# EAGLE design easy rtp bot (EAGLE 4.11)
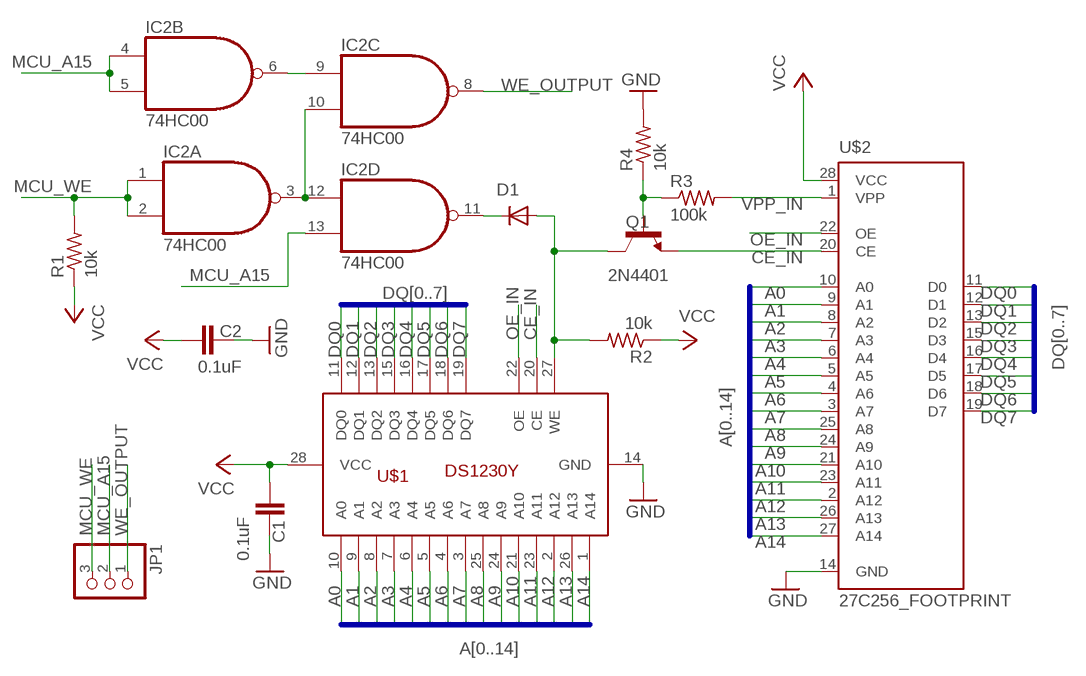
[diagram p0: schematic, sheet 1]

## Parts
C1  0.1uF  C-EU025-024X044  [C025-024X044]
C2  0.1uF  C-EU025-024X044  [C025-024X044]
D1  DIODE-D-2.5  [D-2.5]
IC2  74HC00  7400N  [DIL14]
JP1  PINHD-1X3  [1X03]
Q1  2N4401  2N4416  [TO92]
R1  10k  R-US_0204/2V  [0204V]
R2  10k  R-US_0204/2V  [0204V]
R3  100k  R-US_0204/2V  [0204V]
R4  10k  R-US_0204/2V  [0204V]
U$1  DS1230Y  [DIL28-6]
U$2  27C256_FOOTPRINT  [DIL28-6-FOOTPRINT]

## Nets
A0: U$1.10(A0) U$2.10(A0)
A1: U$1.9(A1) U$2.9(A1)
A2: U$1.8(A2) U$2.8(A2)
A3: U$1.7(A3) U$2.7(A3)
A4: U$1.6(A4) U$2.6(A4)
A5: U$1.5(A5) U$2.5(A5)
A6: U$1.4(A6) U$2.4(A6)
A7: U$1.3(A7) U$2.3(A7)
A8: U$1.25(A8) U$2.25(A8)
A9: U$1.24(A9) U$2.24(A9)
A10: U$1.21(A10) U$2.21(A10)
A11: U$1.23(A11) U$2.23(A11)
A12: U$1.2(A12) U$2.2(A12)
A13: U$1.26(A13) U$2.26(A13)
A14: U$1.1(A14) U$2.27(A14)
CE_IN: Q1.3(E) U$1.20(CE) U$2.20(CE)
DQ0: U$1.11(DQ0) U$2.11(D0)
DQ1: U$1.12(DQ1) U$2.12(D1)
DQ2: U$1.13(DQ2) U$2.13(D2)
DQ3: U$1.15(DQ3) U$2.15(D3)
DQ4: U$1.16(DQ4) U$2.16(D4)
DQ5: U$1.17(DQ5) U$2.17(D5)
DQ6: U$1.18(DQ6) U$2.18(D6)
DQ7: U$1.19(DQ7) U$2.19(D7)
GND: C1.2 C2.2 R4.2 U$1.14(GND) U$2.14(GND)
MCU_A15: IC2.4(B:I0) IC2.5(B:I1) IC2.13(D:I1) JP1.2
MCU_WE: IC2.1(A:I0) IC2.2(A:I1) JP1.3 R1.2
N$3: Q1.2(B) R3.1 R4.1
N$4: D1.C IC2.11(D:O)
N$5: IC2.6(B:O) IC2.9(C:I0)
N$7: D1.A Q1.1(C) R2.2 U$1.27(WE)
N$8: IC2.3(A:O) IC2.10(C:I1) IC2.12(D:I0)
OE_IN: U$1.22(OE) U$2.22(OE)
VCC: C1.1 C2.1 R1.1 R2.1 U$1.28(VCC) U$2.28(VCC)
VPP_IN: R3.2 U$2.1(VPP)
WE_OUTPUT: IC2.8(C:O) JP1.1

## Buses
DQ[0..7]
A[0..14]

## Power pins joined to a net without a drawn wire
GND: IC2.7(P:GND)
VCC: IC2.14(P:VCC)

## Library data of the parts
C1 C2 = rcl:C-EU: CAPACITOR, European symbol
D1 = diode:DIODE-: DIODE
IC2 = 74xx-us:74*00: Quad 2-input NAND gate
JP1 = pinhead:PINHD-1X3: PIN HEADER
Q1 = transistor-npn:2N4416: NPN Transistor
R1-R4 = rcl:R-US_: RESISTOR, American symbol
U$1 = NVSRAM:DS1230*
U$2 = NVSRAM:27C256_FOOTPRINT: This is a footprint of a 27C256. It has .040" drills for pins so that it can be used with wirewrap sockets.

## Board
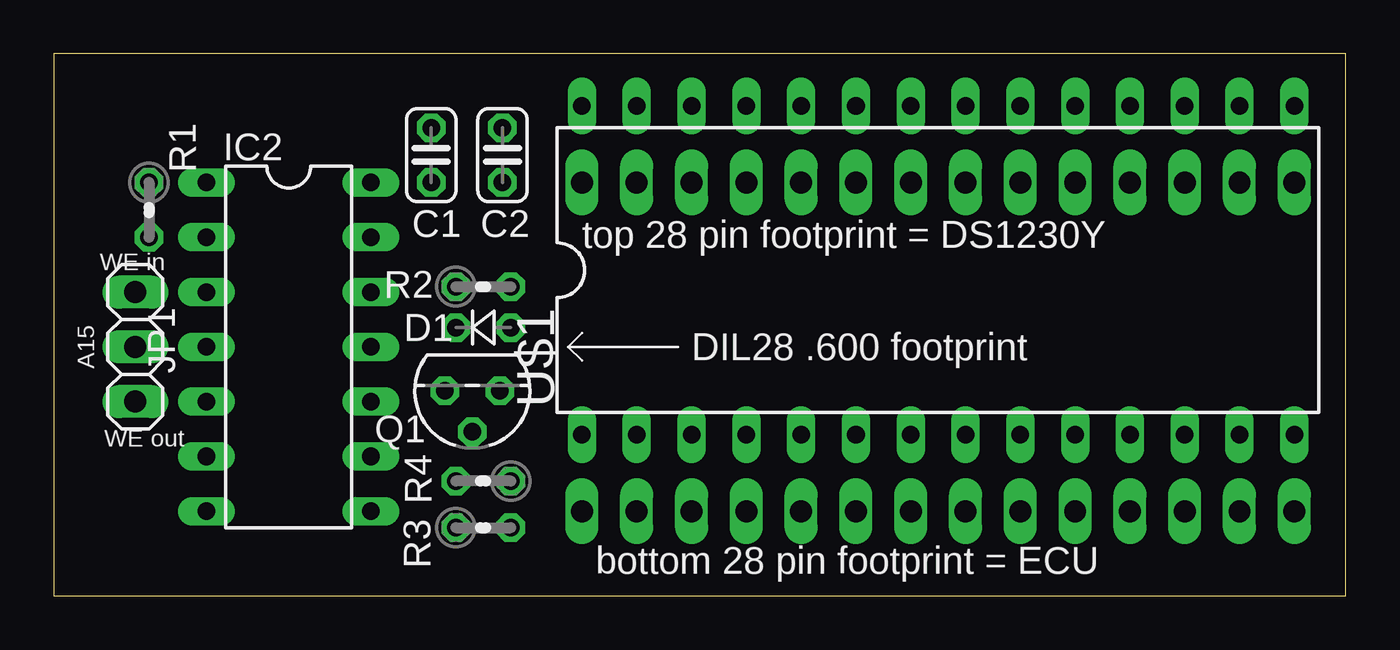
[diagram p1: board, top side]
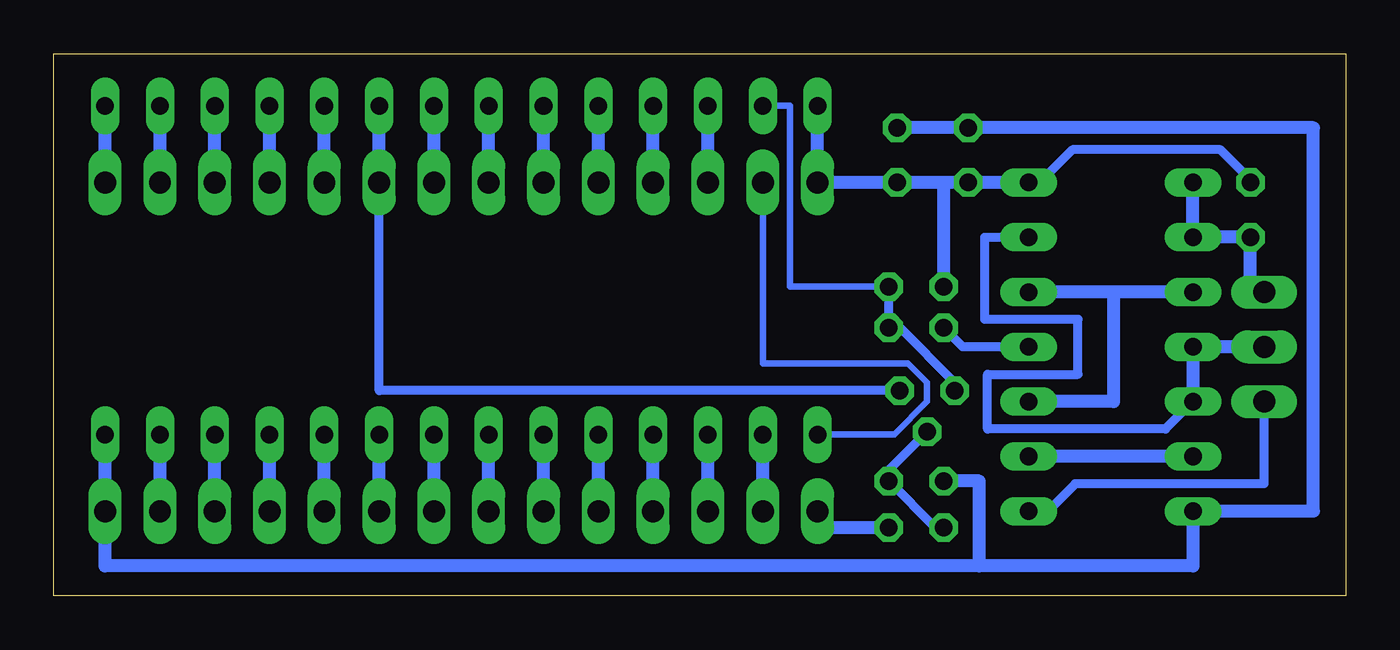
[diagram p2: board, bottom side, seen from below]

Size 59.87 x 25.14 mm. Coordinates in mm from the lower left corner, seen from the top.
Outline: 0,0 59.87,0 59.87,25.14 0,25.14 0,0
Copper layers (1*16): Top 0.035mm / dielectric 1.5mm / Bottom 0.035mm
Design rules "default": minimum track width 10mil, minimum drill 24mil, track to track 8mil, track to pad 8mil, pad to pad 8mil, via to via 8mil, smd to smd 8mil, copper to edge 40mil, drill to drill 8mil, minimum pad ring 10mil, minimum via ring 8mil, stop-mask expansion 4mil, vias tented up to drill 0mil, thermal gap 10mil

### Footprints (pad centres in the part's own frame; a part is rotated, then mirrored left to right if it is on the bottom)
C025-024X044 = drill 0.813 octagon: 1 -1.27,0; 2 1.27,0
D-2.5 = drill 0.813 octagon: A 1.27,0; C -1.27,0
DIL14 = drill 0.813 long: 1 -7.62,-3.81; 2 -5.08,-3.81; 3 -2.54,-3.81; 4 0,-3.81; 5 2.54,-3.81; 6 5.08,-3.81; 7 7.62,-3.81; 8 7.62,3.81; 9 5.08,3.81; 10 2.54,3.81; 11 0,3.81; 12 -2.54,3.81; 13 -5.08,3.81; 14 -7.62,3.81
1X03 = drill 1.016 long: 1 -2.54,0; 2 0,0; 3 2.54,0
TO92 = drill 0.813 octagon: 1 1.27,0; 2 0,1.905; 3 -1.27,0
0204V = drill 0.813 octagon: 1 -1.27,0; 2 1.27,0
DIL28-6 = drill 0.813 long: 1 -16.51,-7.62; 2 -13.97,-7.62; 3 -11.43,-7.62; 4 -8.89,-7.62; 5 -6.35,-7.62; 6 -3.81,-7.62; 7 -1.27,-7.62; 8 1.27,-7.62; 9 3.81,-7.62; 10 6.35,-7.62; 11 8.89,-7.62; 12 11.43,-7.62; 13 13.97,-7.62; 14 16.51,-7.62; 15 16.51,7.62; 16 13.97,7.62; 17 11.43,7.62; 18 8.89,7.62; 19 6.35,7.62; 20 3.81,7.62; 21 1.27,7.62; 22 -1.27,7.62; 23 -3.81,7.62; 24 -6.35,7.62; 25 -8.89,7.62; 26 -11.43,7.62; 27 -13.97,7.62; 28 -16.51,7.62
DIL28-6-FOOTPRINT = drill 1.016 long: 1 -16.51,-7.62; 2 -13.97,-7.62; 3 -11.43,-7.62; 4 -8.89,-7.62; 5 -6.35,-7.62; 6 -3.81,-7.62; 7 -1.27,-7.62; 8 1.27,-7.62; 9 3.81,-7.62; 10 6.35,-7.62; 11 8.89,-7.62; 12 11.43,-7.62; 13 13.97,-7.62; 14 16.51,-7.62; 15 16.51,7.62; 16 13.97,7.62; 17 11.43,7.62; 18 8.89,7.62; 19 6.35,7.62; 20 3.81,7.62; 21 1.27,7.62; 22 -1.27,7.62; 23 -3.81,7.62; 24 -6.35,7.62; 25 -8.89,7.62; 26 -11.43,7.62; 27 -13.97,7.62; 28 -16.51,7.62

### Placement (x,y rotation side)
C1  17.49,20.44 90 top
C2  20.79,20.44 90 top
D1  19.9,12.44 0 top
IC2  10.88,11.55 270 top
JP1  3.77,11.55 90 top
Q1  19.39,9.52 180 top
R1  4.41,17.9 270 top
R2  19.9,14.35 0 top
R3  19.9,3.17 0 top
R4  19.9,5.33 180 top
U$1  40.98,15.11 0 top
U$2  40.98,11.55 0 top

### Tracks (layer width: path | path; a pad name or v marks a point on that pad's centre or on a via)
A0
  Bottom 0.61: U$2.10 U$1.10
A1
  Bottom 0.61: U$2.9 U$1.9
A2
  Bottom 0.61: U$2.8 U$1.8
A3
  Bottom 0.61: U$2.7 U$1.7
A4
  Bottom 0.61: U$2.6 U$1.6
A5
  Bottom 0.61: U$2.5 U$1.5
A6
  Bottom 0.61: U$2.4 U$1.4
A7
  Bottom 0.61: 29.55,3.81 U$2.3 U$1.3
A8
  Bottom 0.61: U$2.25 U$1.25
A9
  Bottom 0.61: U$2.24 U$1.24
A10
  Bottom 0.61: U$2.21 U$1.21
A11
  Bottom 0.61: U$2.23 U$1.23
A12
  Bottom 0.61: 27.01,7.62 U$1.2 U$2.2
A13
  Bottom 0.61: U$2.26 U$1.26
A14
  Bottom 0.305: U$1.1 20.92,7.49 19.39,9.01 19.39,9.9 20.28,10.79 27.01,10.79 U$2.27
CE_IN
  Bottom 0.406: Q1.3 44.79,9.52 U$2.20
  Bottom 0.61: U$2.20 U$1.20
DQ0
  Bottom 0.61: 49.87,3.81 U$2.11 U$1.11
DQ1
  Bottom 0.61: U$2.12 U$1.12
DQ2
  Bottom 0.61: U$2.13 U$1.13
DQ3
  Bottom 0.61: U$2.15 U$1.15
DQ4
  Bottom 0.61: U$2.16 U$1.16
DQ5
  Bottom 0.61: U$2.17 U$1.17
DQ6
  Bottom 0.61: 49.87,19.05 U$2.18 U$1.18
DQ7
  Bottom 0.61: U$2.19 U$1.19
GND
  Bottom 0.61: U$1.14 U$2.14 57.49,1.39 16.98,1.39 | 16.98,1.39 7.07,1.39 IC2.7 | IC2.7 7.07,4.06 | R4.2 16.98,5.33 16.98,1.39 | C2.2 C1.2 1.49,21.71 1.49,3.93 IC2.7
MCU_A15
  Bottom 0.406: IC2.13 16.73,16.63 16.73,12.82 12.41,12.82 12.41,10.28 16.6,10.28 16.6,7.74 8.34,7.74 IC2.5
  Bottom 0.61: JP1.2 IC2.4 IC2.5 7.07,8.88
MCU_WE
  Bottom 0.61: IC2.2 7.07,16.76 | IC2.2 IC2.1 | JP1.3 4.41,14.09 R1.2 IC2.2
N$3
  Bottom 0.406: R3.1 19.01,3.17 R4.1 21.17,5.84 Q1.2
N$4
  Bottom 0.406: IC2.11 17.74,11.55 D1.C
N$5
  Bottom 0.61: IC2.6 IC2.9
N$7
  Bottom 0.305: U$1.27 25.74,22.73 25.74,14.35 R2.2
  Bottom 0.406: R2.2 D1.A 20.66,12.44 18.12,9.9 Q1.1
  Bottom 0.61: R2.2 21.17,14.47
N$8
  Bottom 0.61: IC2.3 10.76,14.09 | 10.76,14.09 IC2.12 | IC2.10 10.76,9.01 10.76,14.09
OE_IN
  Bottom 0.61: U$2.22 U$1.22
VCC
  Bottom 0.406: IC2.14 14.19,19.17 12.66,20.7 5.8,20.7 4.41,19.3 R1.1
  Bottom 0.61: U$1.28 U$2.28 C2.1 18.63,19.17 | 18.63,19.17 C1.1 IC2.14 14.69,19.3 | 18.63,19.17 R2.1
VPP_IN
  Bottom 0.61: R3.2 24.47,3.17 U$2.1
WE_OUTPUT
  Bottom 0.406: JP1.1 3.77,5.2 12.54,5.2 13.8,3.93 IC2.8

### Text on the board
tNames: top 28 pin footprint = DS1230Y | WE in | A15 | WE out | bottom 28 pin footprint = ECU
